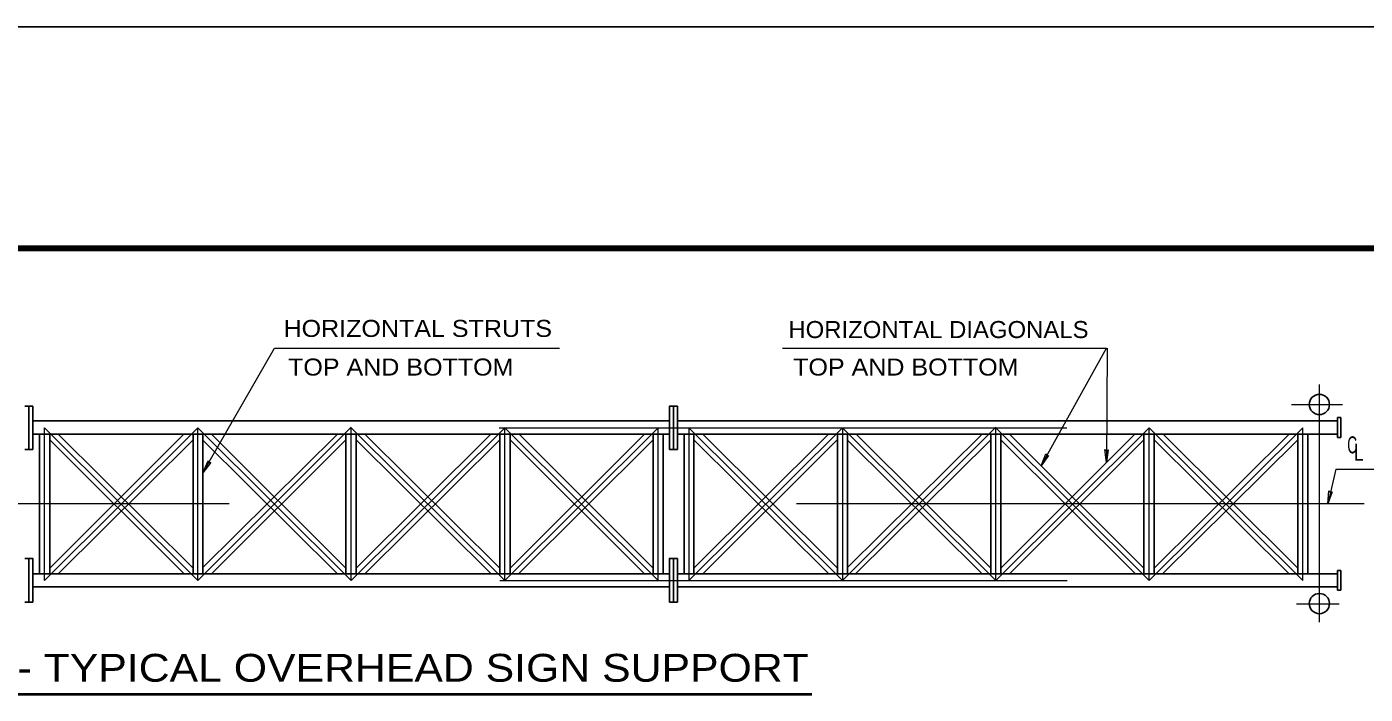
# Model space of a CAD drawing. Extents: x 312601.858 to 312602.699, y 144420.109 to 144420.704.
# Drawn here: x 312602.1757 to 312602.4116, y 144420.586 to 144420.7035 of the extents above; entities that cross this region are included whole.
import ezdxf
from ezdxf.enums import TextEntityAlignment as Align

# ---------------------------------------------------------------- set-up
doc = ezdxf.new("R2010")
doc.units = 0
doc.header["$LTSCALE"] = 0.0012
doc.linetypes.add('DOT_DASHED', pattern=[7.7, 5, -1.2, 0.3, -1.2])
doc.linetypes.add('LONG_DASHED', pattern=[7.5, 6, -1.5])
for name, color, linetype, lineweight in [('1', 7, 'Continuous', 25), ('2', 7, 'Continuous', 13), ('39', 7, 'Continuous', 13)]:
    doc.layers.add(name, color=color, linetype=linetype, lineweight=lineweight)

msp = doc.modelspace()

# ---------------------------------------------------------------- linework, layer by layer
at = {"layer": '1', "lineweight": 13}
for p, q in [((312602.2068, 144420.625), (312602.2194, 144420.6469)), ((312602.2194, 144420.6469), (312602.2696, 144420.6469)), ((312602.3089, 144420.6469), (312602.366, 144420.6469)), ((312602.3545, 144420.6262), (312602.366, 144420.6469)), ((312602.3661, 144420.6469), (312602.366, 144420.6268)), ((312602.4064, 144420.6256), (312602.405, 144420.6195))]:
    msp.add_line(p, q, dxfattribs=at)
at = {"layer": '1', "linetype": 'DOT_DASHED', "lineweight": 13}
for p, q in [((312602.4035, 144420.6405), (312602.4035, 144420.5987)), ((312602.3986, 144420.637), (312602.4076, 144420.637)), ((312602.059, 144420.6329), (312602.4095, 144420.6329)), ((312602.2059, 144420.6329), (312602.1789, 144420.606)), ((312602.1789, 144420.606), (312602.1789, 144420.6329)), ((312602.2059, 144420.6329), (312602.2329, 144420.606)), ((312602.2059, 144420.606), (312602.2059, 144420.6329)), ((312602.2329, 144420.6329), (312602.26, 144420.606)), ((312602.26, 144420.6329), (312602.2329, 144420.606)), ((312602.2329, 144420.606), (312602.2329, 144420.6329)), ((312602.287, 144420.6329), (312602.26, 144420.606)), ((312602.26, 144420.6329), (312602.287, 144420.606)), ((312602.26, 144420.606), (312602.26, 144420.6329)), ((312602.287, 144420.606), (312602.287, 144420.6329)), ((312602.3195, 144420.6329), (312602.2924, 144420.606)), ((312602.2924, 144420.6329), (312602.2924, 144420.606)), ((312602.3195, 144420.6329), (312602.3465, 144420.606)), ((312602.3195, 144420.6329), (312602.3195, 144420.606)), ((312602.3465, 144420.6329), (312602.3735, 144420.606)), ((312602.3735, 144420.6329), (312602.3465, 144420.606)), ((312602.3465, 144420.606), (312602.3465, 144420.6329)), ((312602.4006, 144420.6329), (312602.3735, 144420.606)), ((312602.3735, 144420.6329), (312602.4006, 144420.606)), ((312602.3735, 144420.606), (312602.3735, 144420.6329)), ((312602.4006, 144420.606), (312602.4006, 144420.6329)), ((312602.4114, 144420.6195), (312602.0618, 144420.6195)), ((312602.0591, 144420.606), (312602.4097, 144420.606)), ((312602.3995, 144420.6019), (312602.407, 144420.6019))]:
    msp.add_line(p, q, dxfattribs=at)
at = {"layer": '1'}
for p, q in [((312602.1761, 144420.6367), (312602.1761, 144420.6291)), ((312602.2897, 144420.6367), (312602.2897, 144420.6291)), ((312602.2904, 144420.6367), (312602.2904, 144420.6291)), ((312602.4067, 144420.6347), (312602.4067, 144420.6312)), ((312602.4067, 144420.6347), (312602.4073, 144420.6347)), ((312602.4073, 144420.6347), (312602.4073, 144420.6312)), ((312602.1768, 144420.6341), (312602.289, 144420.6341)), ((312602.2904, 144420.6341), (312602.4067, 144420.6341)), ((312602.1768, 144420.6318), (312602.289, 144420.6318)), ((312602.178, 144420.6072), (312602.178, 144420.6318)), ((312602.1798, 144420.6072), (312602.1798, 144420.6318)), ((312602.2035, 144420.6072), (312602.1798, 144420.6308)), ((312602.2051, 144420.6082), (312602.1813, 144420.6318)), ((312602.2051, 144420.6072), (312602.2051, 144420.6318)), ((312602.2068, 144420.6083), (312602.2305, 144420.6318)), ((312602.2068, 144420.6072), (312602.2068, 144420.6318)), ((312602.2083, 144420.6072), (312602.232, 144420.6308)), ((312602.232, 144420.6072), (312602.232, 144420.6318)), ((312602.2338, 144420.6072), (312602.2338, 144420.6318)), ((312602.2576, 144420.6072), (312602.2338, 144420.6308)), ((312602.2591, 144420.6082), (312602.2353, 144420.6318)), ((312602.2591, 144420.6072), (312602.2591, 144420.6318)), ((312602.2609, 144420.6072), (312602.2609, 144420.6318)), ((312602.2609, 144420.6082), (312602.2846, 144420.6318)), ((312602.2624, 144420.6072), (312602.2861, 144420.6308)), ((312602.2861, 144420.6072), (312602.2861, 144420.6318)), ((312602.2879, 144420.6072), (312602.2879, 144420.6318)), ((312602.2904, 144420.6318), (312602.4067, 144420.6318)), ((312602.2916, 144420.6072), (312602.2916, 144420.6318)), ((312602.2933, 144420.6072), (312602.2933, 144420.6318)), ((312602.3171, 144420.6072), (312602.2933, 144420.6308)), ((312602.3186, 144420.6082), (312602.2949, 144420.6318)), ((312602.3186, 144420.6072), (312602.3186, 144420.6318)), ((312602.3204, 144420.6083), (312602.3441, 144420.6318)), ((312602.3204, 144420.6072), (312602.3204, 144420.6318)), ((312602.3218, 144420.6072), (312602.3456, 144420.6308)), ((312602.3456, 144420.6072), (312602.3456, 144420.6318)), ((312602.3474, 144420.6072), (312602.3474, 144420.6318)), ((312602.3711, 144420.6072), (312602.3474, 144420.6308)), ((312602.3726, 144420.6082), (312602.3489, 144420.6318)), ((312602.3726, 144420.6072), (312602.3726, 144420.6318)), ((312602.3744, 144420.6072), (312602.3744, 144420.6318)), ((312602.3744, 144420.6082), (312602.3982, 144420.6318)), ((312602.3759, 144420.6072), (312602.3997, 144420.6308)), ((312602.3997, 144420.6072), (312602.3997, 144420.6318)), ((312602.4015, 144420.6072), (312602.4015, 144420.6318)), ((312602.4067, 144420.6312), (312602.4073, 144420.6312)), ((312602.1754, 144420.6291), (312602.1768, 144420.6291)), ((312602.2904, 144420.6291), (312602.289, 144420.6291)), ((312602.1761, 144420.6099), (312602.1761, 144420.6022)), ((312602.2897, 144420.6099), (312602.2897, 144420.6022)), ((312602.2904, 144420.6099), (312602.2904, 144420.6022)), ((312602.1768, 144420.6072), (312602.289, 144420.6072)), ((312602.2904, 144420.6072), (312602.4067, 144420.6072)), ((312602.4067, 144420.6078), (312602.4067, 144420.6043)), ((312602.4067, 144420.6078), (312602.4073, 144420.6078)), ((312602.4073, 144420.6078), (312602.4073, 144420.6043)), ((312602.1768, 144420.6049), (312602.289, 144420.6049)), ((312602.2904, 144420.6049), (312602.4067, 144420.6049)), ((312602.4067, 144420.6043), (312602.4073, 144420.6043)), ((312602.1754, 144420.6022), (312602.1768, 144420.6022)), ((312602.2904, 144420.6022), (312602.289, 144420.6022))]:
    msp.add_line(p, q, dxfattribs=at)
at = {"layer": '1', "linetype": 'LONG_DASHED'}
for p, q in [((312602.1798, 144420.6082), (312602.2034, 144420.6318)), ((312602.1813, 144420.6072), (312602.205, 144420.6307)), ((312602.2305, 144420.6072), (312602.2067, 144420.6308)), ((312602.232, 144420.6082), (312602.2083, 144420.6318)), ((312602.2338, 144420.6082), (312602.2575, 144420.6318)), ((312602.2353, 144420.6072), (312602.2591, 144420.6308)), ((312602.2846, 144420.6072), (312602.2609, 144420.6308)), ((312602.2861, 144420.6082), (312602.2625, 144420.6318)), ((312602.2933, 144420.6082), (312602.317, 144420.6318)), ((312602.2949, 144420.6072), (312602.3185, 144420.6307)), ((312602.3441, 144420.6072), (312602.3203, 144420.6308)), ((312602.3456, 144420.6082), (312602.3219, 144420.6318)), ((312602.3474, 144420.6082), (312602.371, 144420.6318)), ((312602.3489, 144420.6072), (312602.3726, 144420.6308)), ((312602.3982, 144420.6072), (312602.3744, 144420.6308)), ((312602.3997, 144420.6082), (312602.376, 144420.6318))]:
    msp.add_line(p, q, dxfattribs=at)
at = {"layer": '1'}
for points in [[(312602.1754, 144420.6367), (312602.1768, 144420.6367), (312602.1768, 144420.6291)], [(312602.2904, 144420.6367), (312602.289, 144420.6367), (312602.289, 144420.6291)], [(312602.1754, 144420.6099), (312602.1768, 144420.6099), (312602.1768, 144420.6022)], [(312602.2904, 144420.6099), (312602.289, 144420.6099), (312602.289, 144420.6022)]]:
    msp.add_lwpolyline(points, dxfattribs=at)
at = {"layer": '1', "linetype": 'DOT_DASHED', "lineweight": 13}
for points in [[(312602.1789, 144420.6329), (312602.2059, 144420.606), (312602.2329, 144420.633)], [(312602.2924, 144420.6329), (312602.3195, 144420.606), (312602.3465, 144420.633)]]:
    msp.add_lwpolyline(points, dxfattribs=at)
at = {"layer": '1', "lineweight": 13}
for points in [[(312602.3558, 144420.628), (312602.3545, 144420.6262), (312602.3553, 144420.6283), (312602.3555, 144420.628)], [(312602.3663, 144420.629), (312602.366, 144420.6268), (312602.3657, 144420.6291), (312602.366, 144420.6288)], [(312602.2082, 144420.6268), (312602.2068, 144420.625), (312602.2077, 144420.6271), (312602.2078, 144420.6268)], [(312602.4058, 144420.6216), (312602.405, 144420.6195), (312602.4052, 144420.6218), (312602.4055, 144420.6215)]]:
    msp.add_lwpolyline(points, close=True, dxfattribs=at)
msp.add_lwpolyline([(312602.4064, 144420.6256), (312602.4294, 144420.6256), (312602.4299, 144420.6256)], dxfattribs=at)
at = {"layer": '1'}
for centre in [(312602.40352, 144420.63701), (312602.40352, 144420.60195)]:
    msp.add_circle(centre, 0.00178, dxfattribs=at)
at = {"layer": '2', "lineweight": 40}
msp.add_line((312602.1509, 144420.586), (312602.3141, 144420.586), dxfattribs=at)
at = {"layer": '39', "lineweight": 25}
msp.add_line((312601.8578, 144420.7035), (312602.6988, 144420.7035), dxfattribs=at)
at = {"layer": '39', "lineweight": 158}
msp.add_line((312601.9088, 144420.6645), (312602.6838, 144420.6645), dxfattribs=at)

# ---------------------------------------------------------------- texts
at = {"layer": '2'}
for s, height, width, p in [('HORIZONTAL STRUTS', 0.003, 1.1, (312602.24465, 144420.6489)), ('HORIZONTAL DIAGONALS', 0.003, 1.05, (312602.3364, 144420.6487)), ('TOP AND BOTTOM', 0.003, 1.1, (312602.24165, 144420.6421)), ('TOP AND BOTTOM', 0.003, 1.1, (312602.33065, 144420.6421)), ('C', 0.003, 0.6, (312602.4093, 144420.6284)), ('L', 0.003, 0.75, (312602.41045, 144420.6271)), ('PLAN - TYPICAL OVERHEAD SIGN SUPPORT', 0.0049, 1.15, (312602.23295, 144420.5882))]:
    msp.add_text(s, height=height, dxfattribs=dict(at, width=width)).set_placement(p, align=Align.CENTER)

doc.saveas('drawing.dxf')
